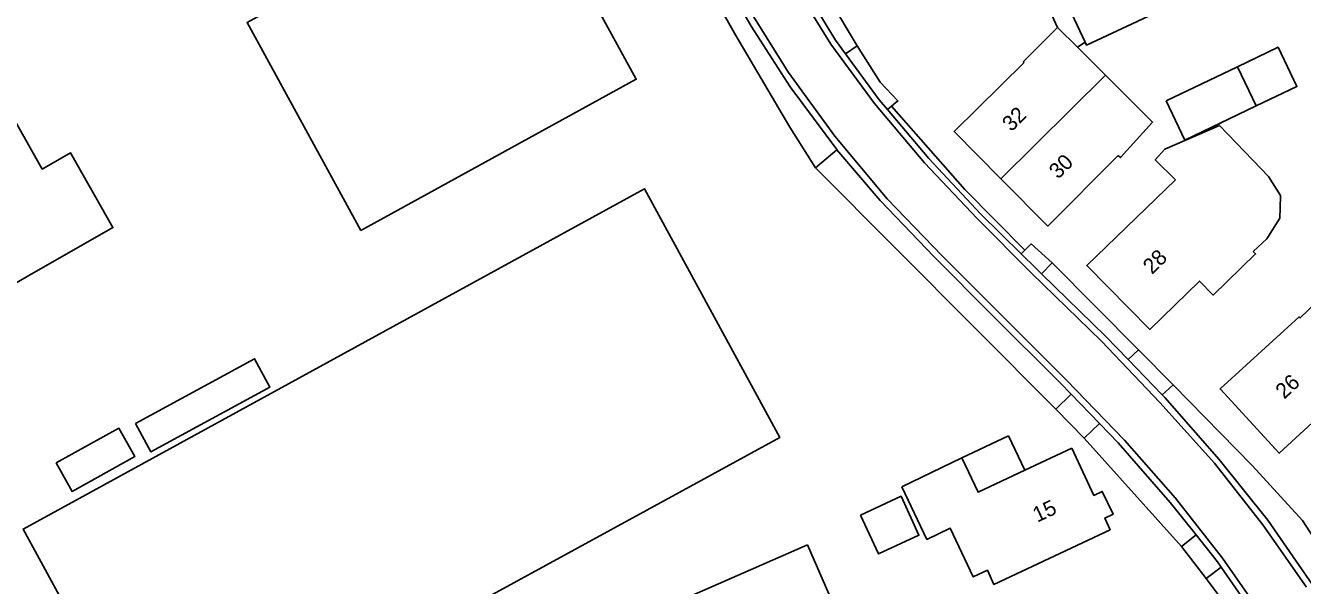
# Model space of a CAD drawing. Extents: x 194485 to 197793, y 468269 to 470822.
# Drawn here: x 195037.7 to 195137.1, y 469309.2 to 469352.8 of the extents above; entities that cross this region are included whole.
import ezdxf

# ---------------------------------------------------------------- set-up
doc = ezdxf.new("R2010")
doc.units = 0
for name, color, linetype in [('BGT grensvlak gebouwinstallatie plus 1', 7, 'Continuous'), ('BGT grensvlak onbegroeid terreindeel', 7, 'Continuous'), ('BGT grensvlak overig bouwwerk uitbreiding populatie', 7, 'Continuous'), ('BGT grensvlak pand op maaiveld', 7, 'Continuous'), ('BGT grensvlak pand op maaiveld LR', 7, 'Continuous'), ('BGT grensvlak wegdeel', 7, 'Continuous'), ('BGT tekst huisnummerreeks', 7, 'Continuous')]:
    doc.layers.add(name, color=color, linetype=linetype)

msp = doc.modelspace()

# ---------------------------------------------------------------- linework, layer by layer
at = {"layer": 'BGT grensvlak gebouwinstallatie plus 1'}
for p, q in [((195118.038, 469352.62), (195117.163, 469354.531)), ((195120.182, 469351.476), (195119.588, 469351.075)), ((195114.233, 469320.822), (195110.586, 469319.1)), ((195115.498, 469318.143), (195114.233, 469320.822))]:
    msp.add_line(p, q, dxfattribs=at)
for points in [[(195132.063, 469349.56), (195135.22, 469351.073), (195136.681, 469348.025), (195133.524, 469346.512)], [(195046.221, 469321.771), (195055.492, 469326.822), (195056.694, 469324.616), (195047.422, 469319.565), (195046.221, 469321.771)], [(195040.052, 469318.707), (195044.934, 469321.417), (195046.161, 469319.206), (195041.279, 469316.495), (195040.052, 469318.707)]]:
    msp.add_lwpolyline(points, dxfattribs=at)
at = {"layer": 'BGT grensvlak onbegroeid terreindeel'}
for p, q in [((195117.912, 469322.903), (195099.187, 469341.675)), ((195124.337, 469327.512), (195117.624, 469334.28)), ((195120.114, 469320.649), (195127.705, 469312.215))]:
    msp.add_line(p, q, dxfattribs=at)
for points in [[(195102.429, 469351.17), (195100.292, 469354.767), (195098.678, 469357.964)], [(195105.101, 469346.485), (195110.829, 469340.003), (195115.503, 469335.286)], [(195127.038, 469324.788), (195133.198, 469318.503), (195137.113, 469314.221), (195140.596, 469308.854), (195142.187, 469306.278), (195145.978, 469299.143), (195149.824, 469290.569)], [(195134.171, 469303.664), (195131.306, 469307.468), (195129.622, 469309.715)]]:
    msp.add_lwpolyline(points, dxfattribs=at)
at = {"layer": 'BGT grensvlak overig bouwwerk uitbreiding populatie'}
msp.add_lwpolyline([(195102.691, 469314.652), (195104.09, 469311.626), (195107.248, 469313.085), (195105.849, 469316.111), (195102.691, 469314.652)], dxfattribs=at)
at = {"layer": 'BGT grensvlak pand op maaiveld'}
for p, q in [((195118.461, 469355.151), (195120.182, 469351.476)), ((195118.038, 469352.62), (195119.588, 469351.075)), ((195119.588, 469351.075), (195121.771, 469348.9)), ((195126.503, 469346.894), (195132.063, 469349.56)), ((195132.063, 469349.56), (195133.524, 469346.512)), ((195105.913, 469316.852), (195110.586, 469319.1)), ((195115.498, 469318.143), (195119.147, 469319.858)), ((195098.572, 469312.337), (195109.44, 469287.479))]:
    msp.add_line(p, q, dxfattribs=at)
for points in [[(195029.704, 469358.019), (195038.96, 469341.587), (195041.169, 469342.84), (195044.461, 469337.03), (195031.095, 469329.403), (195001.477, 469381.966)], [(195063.786, 469336.815), (195054.913, 469353.004), (195076.354, 469364.755), (195085.221, 469348.577), (195063.786, 469336.815)], [(195120.182, 469351.476), (195120.29, 469351.244), (195130.622, 469356.082), (195128.788, 469359.999)], [(195115.432, 469349.891), (195115.376, 469349.948), (195118.038, 469352.62)], [(195113.636, 469340.838), (195109.984, 469344.524), (195115.432, 469349.891)], [(195121.771, 469348.9), (195125.438, 469345.247), (195122.94, 469342.485), (195122.768, 469342.653)], [(195133.524, 469346.512), (195127.965, 469343.846), (195126.503, 469346.894)], [(195127.238, 469340.747), (195125.645, 469342.318), (195126.403, 469343.138), (195130.657, 469344.984), (195133.258, 469342.28)], [(195122.768, 469342.653), (195117.288, 469337.153), (195113.636, 469340.838)], [(195133.258, 469342.28), (195134.473, 469341.017), (195135.42, 469339.538), (195135.384, 469338.577)], [(195070.371, 469306.461), (195096.409, 469320.686), (195085.873, 469340.037), (195037.462, 469313.559), (195047.994, 469294.266), (195065.276, 469303.681)], [(195127.238, 469340.747), (195120.322, 469334.075), (195125.218, 469329.108), (195129.102, 469332.868), (195130.15, 469331.781), (195133.468, 469334.982), (195133.291, 469335.162)], [(195135.384, 469338.577), (195135.354, 469337.757), (195134.33, 469336.157), (195133.291, 469335.162)], [(195138.791, 469331.767), (195136.931, 469330.006), (195136.854, 469330.082), (195130.704, 469324.467), (195135.31, 469319.468), (195141.397, 469325.083), (195139.24, 469327.526), (195141.062, 469329.185)], [(195105.913, 469316.852), (195107.861, 469312.761), (195109.688, 469313.63), (195111.478, 469309.84), (195112.584, 469310.35), (195113.088, 469309.256), (195122.136, 469313.515), (195121.716, 469314.411), (195122.363, 469314.712), (195121.527, 469316.493), (195120.875, 469316.186), (195119.147, 469319.858)], [(195110.586, 469319.1), (195111.848, 469316.427), (195115.498, 469318.143)], [(195098.572, 469312.337), (195083.457, 469305.727), (195083.864, 469304.825), (195045.017, 469287.736), (195021.621, 469276.819), (195022.152, 469275.677)]]:
    msp.add_lwpolyline(points, dxfattribs=at)
at = {"layer": 'BGT grensvlak pand op maaiveld LR'}
msp.add_line((195121.771, 469348.9), (195113.636, 469340.838), dxfattribs=at)
at = {"layer": 'BGT grensvlak wegdeel'}
for p, q in [((195100.373, 469351.311), (195096.974, 469356.865)), ((195097.094, 469349.1), (195093.363, 469355.047)), ((195103.778, 469346.68), (195100.373, 469351.311)), ((195101.526, 469350.571), (195102.429, 469351.17)), ((195100.687, 469344.16), (195097.094, 469349.1)), ((195107.688, 469342.075), (195103.778, 469346.68)), ((195104.787, 469346.229), (195105.101, 469346.485)), ((195104.777, 469339.267), (195100.687, 469344.16)), ((195100.86, 469343.092), (195099.187, 469341.675)), ((195111.779, 469337.745), (195107.688, 469342.075)), ((195109.046, 469334.842), (195104.777, 469339.267)), ((195116.011, 469333.471), (195111.779, 469337.745)), ((195115.203, 469334.989), (195115.503, 469335.286)), ((195113.368, 469330.522), (195109.046, 469334.842)), ((195116.78, 469333.436), (195117.624, 469334.28)), ((195121.462, 469328.185), (195116.011, 469333.471)), ((195118.717, 469325.191), (195113.368, 469330.522)), ((195126.011, 469323.427), (195121.462, 469328.185)), ((195123.534, 469326.757), (195124.337, 469327.512)), ((195127.038, 469324.788), (195124.337, 469327.512)), ((195126.201, 469324.01), (195123.534, 469326.757)), ((195123.244, 469320.486), (195118.717, 469325.191)), ((195117.912, 469322.903), (195119.089, 469324.069)), ((195121.308, 469321.785), (195119.089, 469324.069)), ((195126.201, 469324.01), (195127.038, 469324.788)), ((195130.27, 469318.689), (195126.011, 469323.427)), ((195117.912, 469322.903), (195120.114, 469320.649)), ((195121.308, 469321.785), (195120.114, 469320.649)), ((195127.226, 469315.971), (195123.244, 469320.486)), ((195134.024, 469313.882), (195130.27, 469318.689)), ((195130.9, 469311.3), (195127.226, 469315.971)), ((195127.705, 469312.215), (195128.829, 469313.107)), ((195137.426, 469309.05), (195134.024, 469313.882)), ((195127.705, 469312.215), (195129.622, 469309.715)), ((195134.07, 469306.742), (195130.9, 469311.3)), ((195130.789, 469310.596), (195129.622, 469309.715))]:
    msp.add_line(p, q, dxfattribs=at)
for points in [[(195100.86, 469343.092), (195100.838, 469343.119), (195097.221, 469347.979), (195094.179, 469352.71), (195091.228, 469357.865), (195091.158, 469357.99)], [(195099.187, 469341.675), (195097.185, 469344.852), (195092.986, 469351.974), (195089.961, 469357.321)], [(195101.526, 469350.571), (195100.752, 469351.629), (195097.411, 469357.093), (195097.365, 469357.176)], [(195102.429, 469351.17), (195104.213, 469348.359), (195105.607, 469346.897), (195105.101, 469346.485)], [(195104.787, 469346.229), (195104.159, 469346.976), (195101.526, 469350.571)], [(195115.203, 469334.989), (195112.052, 469338.104), (195108.005, 469342.407), (195104.787, 469346.229)], [(195119.089, 469324.069), (195118.24, 469324.944), (195112.937, 469330.215), (195108.423, 469334.767), (195104.228, 469339.137), (195100.86, 469343.092)], [(195116.78, 469333.436), (195116.364, 469333.841), (195115.203, 469334.989)], [(195117.624, 469334.28), (195115.983, 469335.764), (195115.503, 469335.286)], [(195123.534, 469326.757), (195121.771, 469328.574), (195116.78, 469333.436)], [(195147.997, 469289.781), (195146.733, 469292.733), (195144.072, 469298.474), (195141.111, 469303.896), (195137.858, 469309.292), (195134.411, 469314.243), (195130.621, 469318.98), (195126.389, 469323.817), (195126.201, 469324.01)], [(195128.829, 469313.107), (195126.815, 469315.631), (195122.773, 469320.276), (195121.308, 469321.785)], [(195130.789, 469310.596), (195130.497, 469311.017), (195128.829, 469313.107)], [(195135.051, 469304.16), (195133.492, 469306.707), (195130.789, 469310.596)]]:
    msp.add_lwpolyline(points, dxfattribs=at)

# ---------------------------------------------------------------- texts
at = {"layer": 'BGT tekst huisnummerreeks'}
for s, rotation, p in [('32', 44.7, (195114.443, 469344.445)), ('30', 44.7, (195118.091, 469340.757)), ('28', 44.6, (195125.403, 469333.343)), ('26', 42.7, (195135.699, 469323.631)), ('15', 25.2, (195116.465, 469314.055))]:
    msp.add_text(s, height=1.2, rotation=rotation, dxfattribs=at).set_placement(p)

doc.saveas('drawing.dxf')
